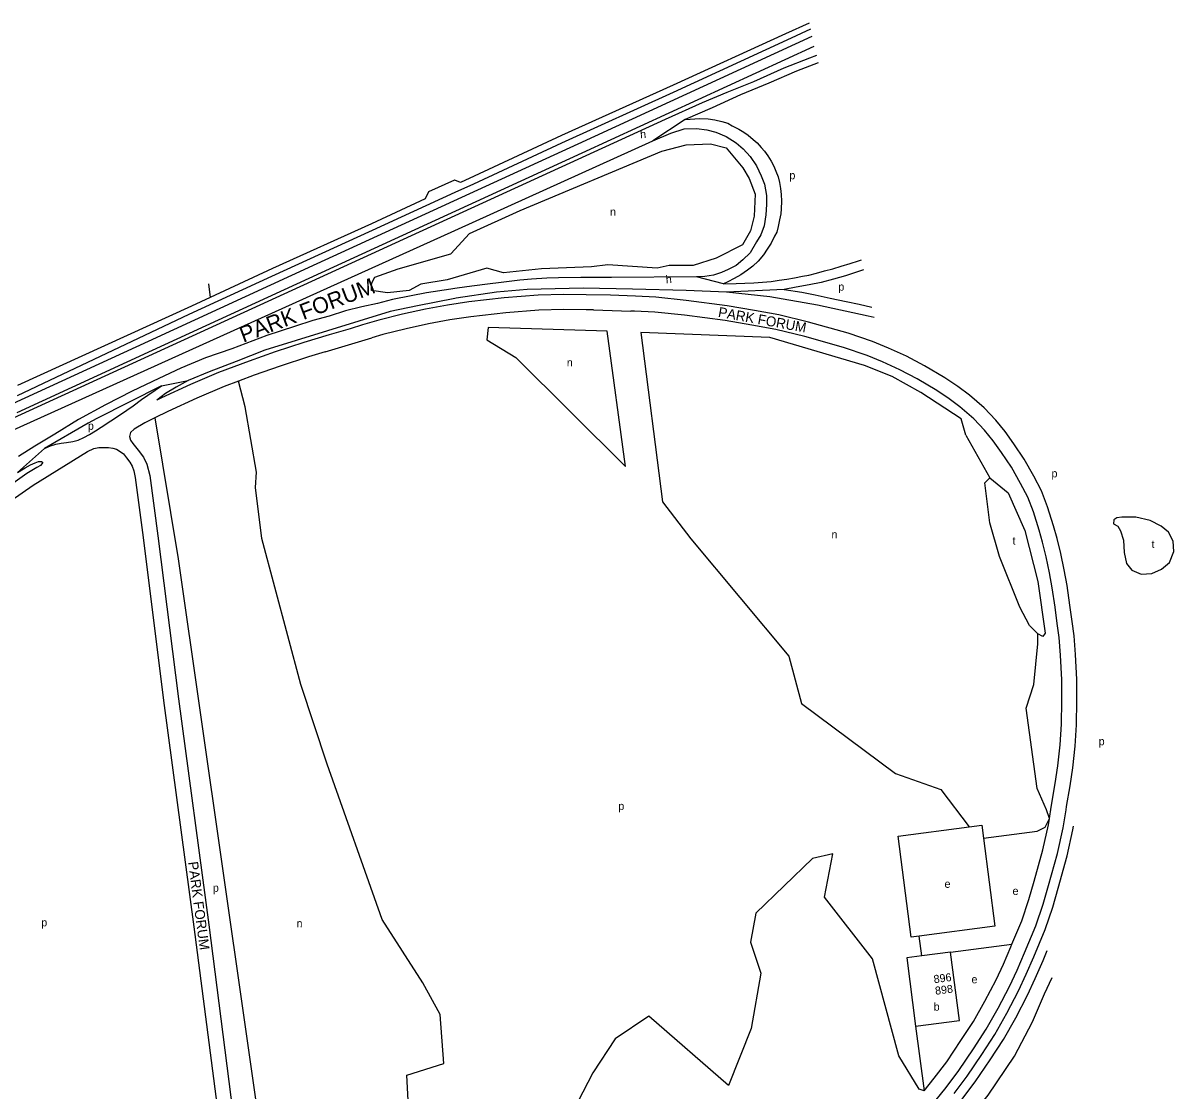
# Model space of a CAD drawing. Extents: x 154320 to 156262, y 382651 to 384180.
# Drawn here: x 155184 to 155759, y 383646 to 384180 of the extents above; entities that cross this region are included whole.
import ezdxf

# ---------------------------------------------------------------- set-up
doc = ezdxf.new("R2010")
doc.units = 0
for name, color, linetype in [('BLT_Basislijn', 7, 'Continuous'), ('BLT_Bebouwing', 7, 'Continuous'), ('BLT_Centroide', 7, 'Continuous'), ('BLT_Huisnummer_reeks', 7, 'Continuous'), ('BLT_Straatnaam', 7, 'Continuous'), ('BLT_Straatnaam_hoofdweg', 7, 'Continuous'), ('BLT_Vlakafsluiter', 7, 'Continuous')]:
    doc.layers.add(name, color=color, linetype=linetype)

msp = doc.modelspace()

# ---------------------------------------------------------------- linework, layer by layer
at = {"layer": 'BLT_Basislijn'}
for p, q in [((155577.18, 384179.93), (155565.34, 384174.49)), ((155577.87, 384176.8), (155565.95, 384171.35)), ((155461.64, 384119.51), (155578.63, 384173.35)), ((155565.34, 384174.49), (155509.17, 384148.86)), ((155565.95, 384171.35), (155509.25, 384145.19)), ((155463.72, 384114.97), (155579.73, 384168.35)), ((155509.17, 384148.86), (155453.31, 384123.64)), ((155509.25, 384145.19), (155453.43, 384119.94)), ((155453.31, 384123.64), (155409.68, 384103.35)), ((155400, 384076.27), (155499.09, 384121.05)), ((155453.43, 384119.94), (155409.3, 384099.45)), ((155400, 384101.36), (155399.87, 384101.41)), ((155400, 384095.17), (155358.79, 384076.23)), ((155409.3, 384099.45), (155400, 384095.17)), ((155358.48, 384079.6), (155308.97, 384057.17)), ((155177.56, 383975.75), (155400, 384076.27)), ((155358.79, 384076.23), (155308.35, 384053.19)), ((155308.97, 384057.17), (155277.73, 384042.72)), ((155308.35, 384053.19), (155267.18, 384034.27)), ((155277.73, 384042.72), (155268.51, 384038.46)), ((155268.51, 384038.46), (155181.49, 383998.69)), ((155267.18, 384034.27), (155200.57, 384002.65)), ((155469.3, 384036.54), (155487.97, 384035.94)), ((155335.24, 384015.63), (155358.58, 384022.61)), ((155200.57, 384002.65), (155181.31, 383993.56)), ((155243.42, 383991.66), (155253.46, 383998.63)), ((155655.52, 383973.85), (155667.44, 383952.5)), ((155657.18, 383778.06), (155663.39, 383778.86)), ((155663.39, 383778.86), (155664.22, 383772.4)), ((155632.16, 383723.49), (155628.14, 383722.97)), ((155633.45, 383713.53), (155632.16, 383723.49)), ((155647.79, 383715.4), (155678.5, 383719.38)), ((155630.37, 383678.35), (155634.56, 383646.03))]:
    msp.add_line(p, q, dxfattribs=at)
for points in [[(155580.75, 384163.74), (155577.26, 384162.4), (155564.51, 384157.44), (155549.4, 384150.58), (155535.94, 384145.15), (155523.65, 384139.95), (155505.23, 384131.68), (155400, 384083.5)], [(155581.58, 384159.96), (155570.89, 384155.78), (155556.95, 384149.87), (155542.78, 384143.97), (155528.61, 384137.59), (155515.15, 384131.68)], [(155515.15, 384131.68), (155522.47, 384132.16)], [(155522.47, 384132.16), (155526.67, 384132.04), (155529.97, 384131.56), (155533.51, 384130.62), (155536.47, 384129.79), (155538.59, 384128.61), (155542.02, 384126.84), (155544.5, 384125.3), (155546.62, 384123.89), (155549.1, 384121.76), (155551.11, 384119.99), (155553.12, 384117.74), (155554.89, 384115.85), (155556.54, 384113.49), (155558.19, 384110.89), (155559.49, 384108.29), (155560.44, 384105.93), (155561.62, 384102.98), (155562.33, 384100.14), (155562.8, 384097.19), (155563.15, 384094.24), (155563.27, 384090.93), (155563.15, 384087.03), (155562.92, 384084.55), (155562.33, 384081.6), (155561.74, 384078.17), (155560.91, 384075.45), (155559.85, 384073.33), (155558.08, 384069.9), (155556.19, 384066.95), (155554.3, 384064), (155551.7, 384060.92), (155548.98, 384058.44), (155546.39, 384056.32), (155542.96, 384054.07), (155539.65, 384052.18), (155536.58, 384050.53), (155534.34, 384049.58)], [(155499.09, 384121.05), (155508.07, 384124.83), (155514.68, 384126.96), (155520.82, 384127.19), (155526.02, 384126.49), (155530.5, 384125.3), (155535.7, 384123.18), (155540.66, 384120.11), (155544.2, 384117.04), (155547.74, 384113.26), (155550.81, 384108.53), (155553.17, 384103.57), (155554.83, 384099.32), (155555.77, 384093.65), (155555.77, 384089.16), (155555.54, 384083.96), (155554.59, 384078.53), (155552.94, 384074.04), (155550.81, 384070.49), (155547.74, 384065.06), (155543.96, 384061.52), (155540.66, 384058.68), (155536.64, 384056.79), (155533.34, 384055.14), (155529.32, 384053.96), (155525.07, 384053.25), (155520.82, 384053.01)], [(155179.2, 383989.79), (155246.91, 384020.95), (155331.29, 384059.78), (155461.64, 384119.51)], [(155181.29, 383985.24), (155249, 384016.41), (155333.38, 384055.23), (155463.72, 384114.97)], [(155399.87, 384101.41), (155386.87, 384095.52), (155385.18, 384091.99), (155358.48, 384079.6)], [(155409.68, 384103.35), (155402.86, 384100.19), (155400, 384101.36)], [(155400, 384083.5), (155127.49, 383958.74)], [(155534.34, 384049.58), (155540.6, 384049.7), (155544.97, 384049.82), (155549.46, 384050.06), (155553.82, 384050.41), (155558.08, 384050.77), (155562.09, 384051.36), (155565.99, 384051.83), (155569.88, 384052.54), (155573.78, 384053.36), (155576.97, 384053.96), (155580.86, 384054.9), (155584.88, 384055.96), (155589.01, 384057.03), (155593.15, 384058.33), (155597.63, 384059.74), (155601.77, 384061.04), (155603.28, 384061.58)], [(155604.38, 384056.57), (155602.24, 384055.85), (155595.39, 384053.6), (155589.25, 384051.83), (155583.23, 384050.29), (155577.21, 384048.99), (155570.71, 384047.81), (155564.69, 384046.75)], [(155520.82, 384053.01), (155478.31, 384052.77), (155462.96, 384052.77), (155451.86, 384052.54), (155445.96, 384052.3), (155438.4, 384051.83), (155432.5, 384051.36), (155424.47, 384050.41), (155415.02, 384049.23), (155406.05, 384048.05), (155400, 384047.16)], [(155400, 384047.16), (155398.02, 384046.87), (155385.97, 384044.98), (155378.18, 384043.56), (155368.97, 384041.67), (155361.41, 384039.78), (155353.62, 384038.12), (155345.35, 384036), (155337.32, 384033.4), (155329.06, 384031.27), (155319.85, 384028.2), (155306.15, 384023.71), (155288.67, 384017.1), (155275.45, 384012.61), (155263.17, 384007.41), (155252.07, 384002.21), (155238.84, 383995.84), (155225.38, 383988.98), (155211.92, 383981.66), (155200.11, 383974.34), (155190.19, 383968.43), (155181.93, 383963.23)], [(155608.83, 384020.76), (155596.57, 384024.95), (155576.81, 384030.41), (155562.02, 384034), (155549.77, 384036.23), (155536.25, 384038.6), (155515.68, 384041.27), (155500.55, 384042.84), (155490.27, 384043.35), (155477.78, 384043.9), (155465.74, 384044.1), (155454.5, 384044.2), (155441.7, 384043.95), (155424.74, 384042.58), (155407.12, 384040.51), (155396.33, 384038.89), (155385.39, 384036.92), (155373.94, 384034.38), (155362.11, 384031.4), (155353.95, 384029.09), (155347.7, 384027.13), (155337.16, 384024.06), (155324.58, 384020.23), (155310.25, 384015.54), (155297.26, 384010.91), (155281.97, 384005.21), (155268, 383999.29), (155253.44, 383992.48), (155251.05, 383991.33)], [(155535.82, 384045.45), (155515.74, 384046.16), (155488.82, 384046.87), (155464.26, 384047.34), (155436.16, 384046.63), (155420.81, 384045.45), (155400.73, 384042.38), (155400, 384042.24)], [(155609.65, 384032.65), (155606.67, 384033.4), (155581.4, 384038.84), (155557.54, 384043.09), (155535.82, 384045.45)], [(155564.69, 384046.75), (155573.43, 384045.45), (155580.16, 384044.03), (155587.71, 384042.38), (155595.63, 384040.73), (155602.12, 384039.31), (155608.5, 384037.88)], [(155400, 384042.24), (155381.37, 384038.6), (155367.67, 384035.77), (155305.09, 384016.39), (155290.68, 384010.72), (155277.22, 384005.52), (155266.83, 384001.27)], [(155469.3, 384036.54), (155465.64, 384036.6), (155454.54, 384036.7), (155442.08, 384036.46), (155425.47, 384035.12), (155408.12, 384033.08), (155397.56, 384031.49), (155386.86, 384029.56), (155375.66, 384027.08), (155364.04, 384024.15), (155358.58, 384022.61)], [(155697.25, 383782.31), (155698.19, 383787.89), (155700.13, 383799.67), (155701.42, 383808.6), (155702.61, 383819.13), (155703.35, 383829.42), (155703.5, 383841.14), (155703.4, 383851.51), (155702.85, 383863.85), (155702.11, 383872.8), (155701.17, 383879.72), (155700.08, 383887.91), (155698.63, 383897.5), (155697.3, 383905.05), (155695.57, 383913.06), (155693.84, 383920.41), (155692.13, 383926.43), (155689.23, 383935.49), (155686.38, 383942.92), (155682.85, 383949.79), (155678.3, 383957.92), (155673.31, 383965.3), (155669.1, 383971.08), (155664.74, 383976.45), (155659.41, 383982.07), (155652.54, 383988.02), (155647.11, 383992.05), (155640.96, 383996.2), (155631.11, 384002.01), (155622.42, 384006.62), (155613.75, 384010.51), (155606.14, 384013.75), (155594.36, 384017.78), (155574.93, 384023.14), (155560.46, 384026.66), (155548.46, 384028.85), (155535.12, 384031.18), (155514.81, 384033.82), (155499.98, 384035.36), (155489.92, 384035.86), (155487.97, 384035.94)], [(155655.52, 383973.85), (155653.17, 383982.04), (155633.04, 383995.19), (155618.61, 384003.14), (155604.81, 384008.8), (155557.48, 384022.74), (155492.94, 384025.29), (155503.77, 383940.57), (155517.99, 383921.98), (155566.92, 383863.48), (155573.31, 383839.67), (155620.35, 383804.82), (155642.99, 383796.69), (155657.18, 383778.06)], [(155705.84, 383788.19), (155707.54, 383798.52), (155708.86, 383807.64), (155710.08, 383818.45), (155710.84, 383829.1), (155711, 383841.13), (155710.89, 383851.71), (155710.34, 383864.32), (155709.57, 383873.61), (155708.61, 383880.72), (155707.5, 383888.96), (155706.04, 383898.71), (155704.66, 383906.49), (155702.89, 383914.71), (155701.11, 383922.3), (155699.31, 383928.6), (155696.3, 383937.98), (155693.24, 383945.99), (155689.46, 383953.34), (155684.69, 383961.85), (155679.45, 383969.61), (155675.05, 383975.65), (155670.38, 383981.4), (155664.6, 383987.5), (155657.23, 383993.88), (155651.44, 383998.17), (155644.96, 384002.54), (155634.77, 384008.55), (155625.72, 384013.36), (155616.76, 384017.38), (155608.83, 384020.76)], [(155335.24, 384015.63), (155326.84, 384013.08), (155312.68, 384008.45), (155299.83, 384003.86), (155291.91, 384000.91)], [(155253.46, 383998.63), (155221.11, 383982.21), (155216.74, 383979.85), (155195.01, 383967.21)], [(155291.91, 384000.91), (155284.75, 383998.24), (155271.06, 383992.43), (155256.66, 383985.71), (155250.11, 383982.53)], [(155266.83, 384001.27), (155260.69, 383997.96), (155255.49, 383994.66), (155251.05, 383991.33)], [(155415.14, 383551.07), (155407.08, 383550.96), (155404.08, 383565.06), (155387.7, 383591.41), (155380.21, 383607.78), (155377.91, 383619.19), (155376.03, 383653.96), (155394.55, 383659.78), (155392.73, 383684.28), (155384.13, 383700.15), (155363.76, 383731.77), (155336.24, 383809.42), (155323.11, 383849.23), (155303.53, 383922.25), (155300.42, 383947.66), (155300.92, 383955.47), (155295.18, 383988.01), (155291.91, 384000.91)], [(155195.01, 383967.21), (155197.96, 383968.51), (155200.56, 383969.34), (155203.27, 383969.93), (155205.99, 383970.28), (155209.18, 383970.75), (155211.78, 383971.46), (155214.61, 383972.64), (155217.44, 383974.18), (155220.51, 383976.07), (155223.35, 383977.84), (155233.03, 383984.22), (155239.29, 383988.47), (155243.42, 383991.66)], [(155250.11, 383982.53), (155245.05, 383980.08), (155239.74, 383976.95)], [(155250.11, 383982.53), (155261.74, 383912.14), (155306.1, 383602.51), (155325.55, 383519.95), (155323.53, 383503)], [(155239.74, 383976.95), (155237.95, 383975.29), (155237.5, 383973.14), (155238, 383971.33), (155239.1, 383969.78), (155241.86, 383966.42), (155244.36, 383962.87), (155246.17, 383959.31), (155247.67, 383953.79)], [(155172.81, 383937.32), (155189.34, 383948.9), (155216.5, 383965.67), (155219.69, 383967.21), (155222.05, 383967.68), (155224.18, 383967.68), (155226.89, 383967.68), (155229.14, 383967.33), (155230.91, 383966.97), (155232.8, 383965.79), (155234.45, 383964.49), (155235.98, 383962.49), (155237.64, 383960.36), (155238.82, 383958.35), (155239.53, 383955.99), (155240.24, 383952.8)], [(155181.43, 383955.28), (155185.33, 383957.64), (155188.04, 383959.06), (155190.28, 383960.12), (155191.94, 383960.71), (155193.47, 383960.71), (155194.06, 383960.24), (155193.71, 383959.53), (155192.88, 383958.7), (155191.11, 383957.76), (155186.15, 383954.69), (155179.18, 383949.73)], [(155240.24, 383952.8), (155244.25, 383922.67), (155254.52, 383841.16), (155269.64, 383728.11), (155281.68, 383634.19), (155294.91, 383531.3), (155295.85, 383521.14)], [(155247.67, 383953.79), (155251.69, 383923.64), (155261.96, 383842.13), (155277.07, 383729.08), (155289.12, 383635.15), (155302.36, 383532.12), (155303.32, 383521.83)], [(155691.37, 383874.5), (155687.29, 383878.7), (155682.45, 383887.92), (155672.26, 383913.22), (155667.42, 383930.12), (155664.87, 383950), (155667.44, 383952.5)], [(155667.44, 383952.5), (155676.67, 383944.99), (155684.99, 383926.3), (155691.37, 383900.74), (155695.1, 383874.84), (155694, 383873.31), (155691.37, 383874.5)], [(155697.25, 383782.31), (155695.84, 383786.53), (155691.19, 383797.27), (155685.68, 383837.34), (155689.45, 383849.25), (155691.42, 383869.56), (155691.37, 383874.5)], [(155637.85, 383638.14), (155645.62, 383647.83), (155652.03, 383656.33), (155659.27, 383667.11), (155665.66, 383676.89), (155671.61, 383687.38), (155677.29, 383698.29), (155681.05, 383706.42), (155684.84, 383715.11), (155690.42, 383728.54), (155694.09, 383739.5), (155696.82, 383748.82), (155701.22, 383764.77), (155704.06, 383777.59), (155705.58, 383786.66), (155705.84, 383788.19)], [(155628.14, 383722.97), (155621.59, 383773.49), (155657.18, 383778.06)], [(155649.57, 383644.77), (155656.1, 383653.43), (155663.43, 383664.35), (155669.93, 383674.29), (155676, 383684.98), (155681.78, 383696.08), (155685.62, 383704.37), (155689.44, 383713.15), (155695.1, 383726.78), (155698.86, 383738), (155701.63, 383747.45), (155706.07, 383763.57), (155708.97, 383776.63), (155709.28, 383778.47)], [(155664.22, 383772.4), (155691.18, 383775.87), (155695.05, 383777.94), (155697.25, 383782.31)], [(155678.5, 383719.38), (155683.39, 383731.17), (155686.93, 383741.75), (155689.61, 383750.87), (155693.94, 383766.58), (155696.7, 383779.02), (155697.25, 383782.31)], [(155664.22, 383772.4), (155669.87, 383728.36), (155632.16, 383723.49)], [(155634.56, 383646.03), (155632.06, 383646.95), (155621.94, 383663.64), (155608.88, 383712.13), (155584.78, 383742.91), (155588.99, 383764.63), (155578.77, 383762.24), (155550.55, 383734.97), (155547.89, 383720.5), (155553.04, 383704.86), (155548.1, 383677.23), (155536.76, 383648.78), (155496.98, 383683.49), (155480.24, 383672.06), (155468.97, 383655.07), (155453.89, 383625.83), (155444.31, 383633.22), (155434.65, 383632.62), (155423.38, 383626.53), (155417.9, 383619.16), (155415.76, 383606.74), (155415.92, 383588.66), (155411.04, 383581.59)], [(155634.56, 383646.03), (155639.7, 383652.44), (155645.92, 383660.68), (155653.01, 383671.25), (155659.25, 383680.8), (155665.02, 383690.96), (155670.56, 383701.59), (155674.21, 383709.49), (155677.94, 383718.04), (155678.5, 383719.38)], [(155645.63, 383631.87), (155653.52, 383641.7), (155660.18, 383650.53), (155667.6, 383661.59), (155674.2, 383671.69), (155680.39, 383682.59), (155686.27, 383693.88), (155690.18, 383702.32), (155694.04, 383711.19), (155696.16, 383716.29)], [(155657.33, 383632.2), (155666.55, 383643.87), (155679.77, 383663.41), (155688.85, 383680.58), (155694.77, 383694.59), (155698.64, 383702.82)]]:
    msp.add_lwpolyline(points, dxfattribs=at)
for points in [[(155360.04, 384052.84), (155371.76, 384056.98), (155398.02, 384064.61), (155407.44, 384074.66), (155432.64, 384086.17), (155503.57, 384115.94), (155515.75, 384119.09), (155527.76, 384119.53), (155535.74, 384117.6), (155544.01, 384107.5), (155547.22, 384102.12), (155550.12, 384094.29), (155549.7, 384083.45), (155547.87, 384076.12), (155543.81, 384069.12), (155530.73, 384062.34), (155519.11, 384058.71), (155507.2, 384058.77), (155501.17, 384057.37), (155476.5, 384058.98), (155468.38, 384057.98), (155443.4, 384057), (155424.43, 384054.98), (155416.08, 384057.35), (155396.29, 384051.5), (155382.98, 384049.46), (155377.23, 384046.18), (155366.46, 384045.11), (155358.42, 384046.17), (155358.47, 384048.53), (155358.51, 384050.05)], [(155476.18, 384025.93), (155416.66, 384027.67), (155416.04, 384021.62), (155430.54, 384012.74), (155485.42, 383958.21)], [(155747.62, 383931.19), (155740.4, 383932.94), (155733.35, 383932.93), (155730.87, 383932.55), (155729.46, 383931.48), (155729.34, 383929.51), (155731.4, 383928.38), (155732.68, 383926.01), (155734.2, 383921.44), (155734.56, 383915.23), (155735.69, 383909.73), (155738.5, 383906.35), (155743.01, 383904.38), (155748.5, 383904.66), (155753.29, 383906.91), (155757.24, 383910.29), (155759.49, 383915.79), (155759.07, 383920.86), (155756.67, 383925.37), (155753.01, 383928.33)]]:
    msp.add_lwpolyline(points, close=True, dxfattribs=at)
at = {"layer": 'BLT_Bebouwing'}
msp.add_line((155647.79, 383715.4), (155633.45, 383713.53), dxfattribs=at)
for points in [[(155630.37, 383678.35), (155652.23, 383681.19), (155647.79, 383715.4)], [(155633.45, 383713.53), (155625.93, 383712.56), (155630.37, 383678.35)]]:
    msp.add_lwpolyline(points, dxfattribs=at)
at = {"layer": 'BLT_Vlakafsluiter'}
for p, q in [((155515.15, 384131.68), (155499.09, 384121.05)), ((155276.88, 384049.6), (155277.73, 384042.72)), ((155534.34, 384049.58), (155520.82, 384053.01)), ((155564.69, 384046.75), (155535.82, 384045.45)), ((155253.46, 383998.63), (155266.83, 384001.27)), ((155195.01, 383967.21), (155181.43, 383955.28))]:
    msp.add_line(p, q, dxfattribs=at)

# ---------------------------------------------------------------- texts
at = {"layer": 'BLT_Centroide'}
for s, rotation, p in [('h', 5, (155492.82, 384122.27)), ('n', 359.5, (155477.63, 384083.6)), ('h', 5, (155505.65, 384049.72)), ('n', 359.5, (155456.01, 384008.27)), ('n', 359.5, (155588.28, 383922.29)), ('n', 359.5, (155320.92, 383727.84))]:
    msp.add_text(s, height=4, rotation=rotation, dxfattribs=at).set_placement(p)
for s, p in [('p', (155567.28, 384101.83)), ('p', (155591.73, 384046.12)), ('p', (155216.64, 383976.58)), ('p', (155698.26, 383952.8)), ('t', (155678.79, 383919.15)), ('t', (155748.3, 383917.46)), ('p', (155721.86, 383818.88)), ('p', (155481.77, 383786.48)), ('e', (155644.8, 383747.6)), ('p', (155279.1, 383745.58)), ('e', (155678.8, 383744.05)), ('p', (155193.35, 383728.31)), ('e', (155658.27, 383699.86)), ('b', (155639.38, 383686.16))]:
    msp.add_text(s, height=4, dxfattribs=at).set_placement(p)
at = {"layer": 'BLT_Huisnummer_reeks'}
for s, p in [('896', (155639.64, 383699.89)), ('898', (155640.35, 383694.11))]:
    msp.add_text(s, height=4, rotation=7.39517, dxfattribs=at).set_placement(p)
at = {"layer": 'BLT_Straatnaam'}
for rotation, p in [(349.69515, (155531.39, 384033.1)), (277.61512, (155266.67, 383760.42))]:
    msp.add_text('PARK FORUM', height=5, rotation=rotation, dxfattribs=at).set_placement(p)
at = {"layer": 'BLT_Straatnaam_hoofdweg'}
msp.add_text('PARK FORUM', height=8, rotation=20.70823, dxfattribs=at).set_placement((155294.3, 384020.05))

doc.saveas('drawing.dxf')
